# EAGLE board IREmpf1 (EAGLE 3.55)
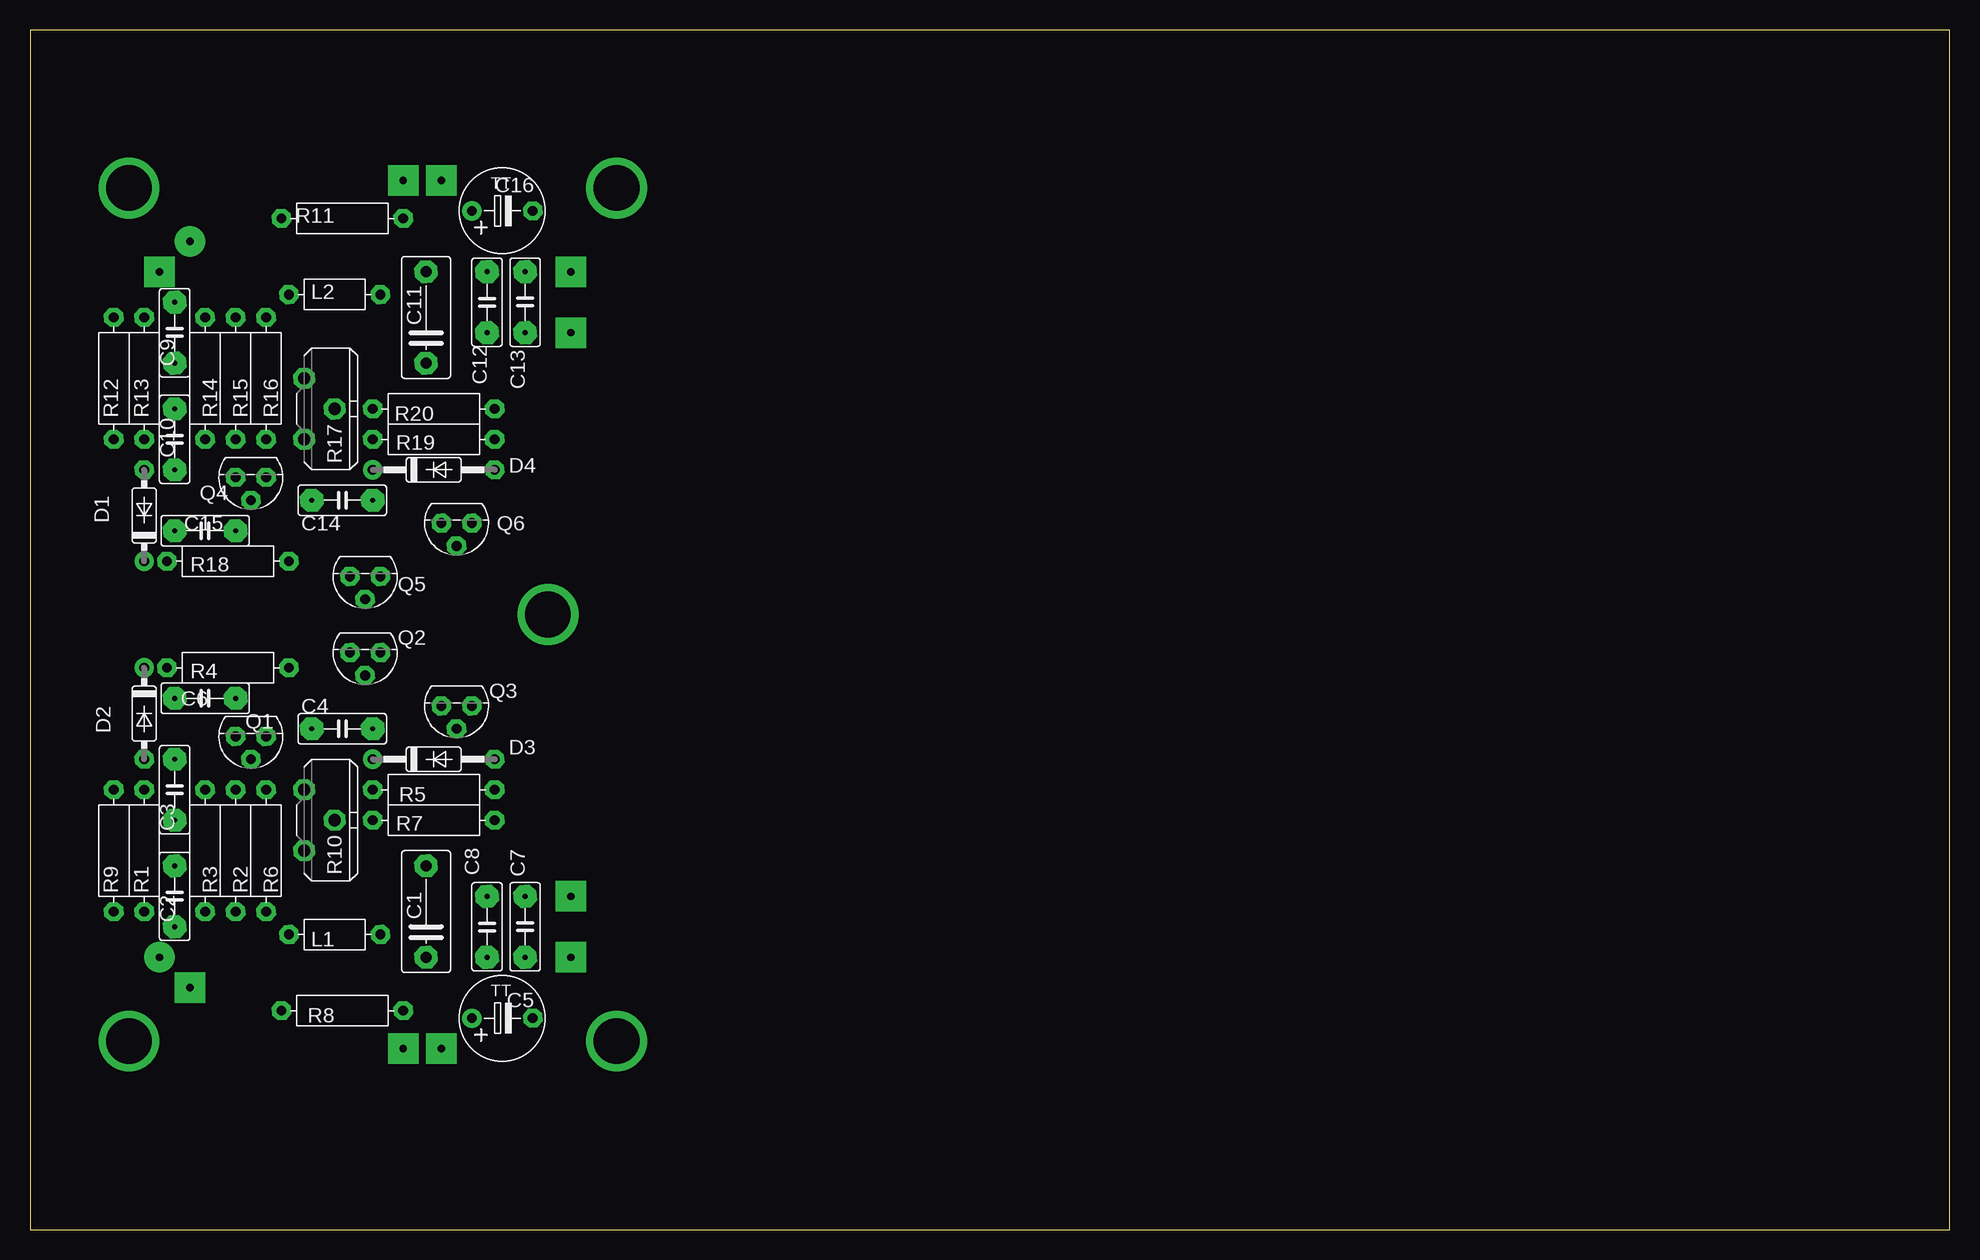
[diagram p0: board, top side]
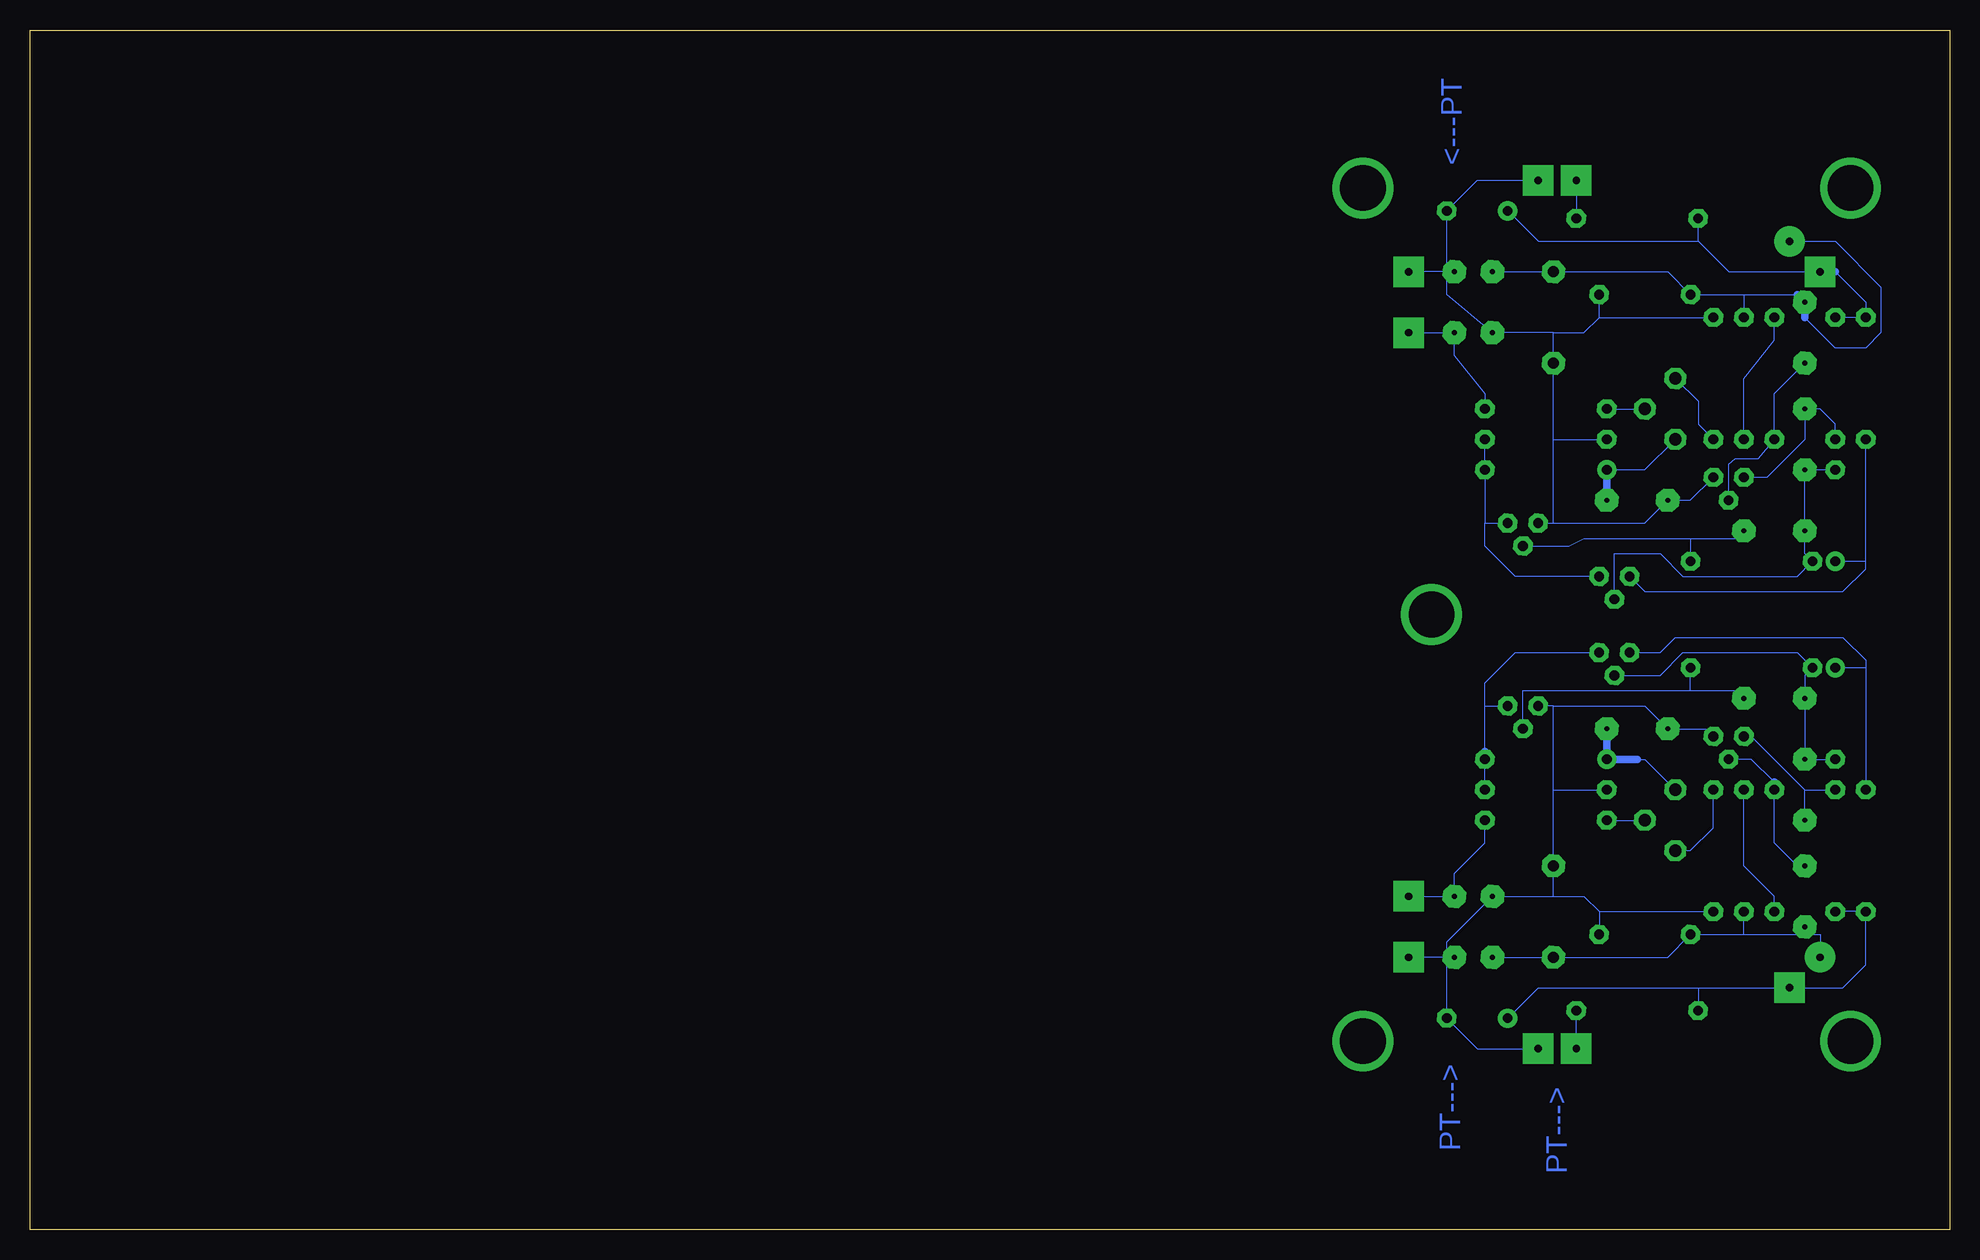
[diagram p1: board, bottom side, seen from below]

Size 160 x 100 mm. Coordinates in mm from the lower left corner, seen from the top.
Outline: 0,0 160,0 160,100 0,100 0,0
Copper layers used: Bottom

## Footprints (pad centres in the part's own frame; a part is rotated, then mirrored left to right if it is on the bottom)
,5B4 = drill 0.914 pad 1.905 octagon:  -3.81,0;  3.81,0
B2,5 = drill 0.406 pad 1.93 octagon:  -2.54,0;  2.54,0
5D7 = drill 0.813 pad 1.6 octagon:  -2.54,0 | drill 0.813 pad 1.6 round:  2.54,0
35-7 = drill 0.813 pad 1.6 round:  -3.81,0 | drill 0.813 pad 1.6 octagon:  3.81,0
35-10 = drill 0.813 pad 1.6 round:  -5.08,0 | drill 0.813 pad 1.6 octagon:  5.08,0
7,5 = drill 0.813 pad 1.6 octagon:  -3.81,0;  3.81,0
92 = drill 0.813 pad 1.6 octagon:  1.27,0;  0,1.905;  -1.27,0
10 = drill 0.813 pad 1.6 octagon:  -5.08,0;  5.08,0
-10S = drill 1.016 pad 1.778 octagon:  -2.54,-1.27;  2.54,-1.27;  0,1.27

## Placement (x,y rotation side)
C1  560p  [,5B4]  33.02,26.5 90 top
C2  0,1æ  [B2,5]  12.06,27.77 90 top
C3  0,1æ  [B2,5]  12.06,36.66 90 top
C4  0,1æ  [B2,5]  26.03,41.74 0 top
C5  47æ  [5D7]  39.37,17.61 180 top
C6  0,1æ  [B2,5]  14.6,44.28 180 top
C7  ??  [B2,5]  41.27,25.23 90 top
C8  ??  [B2,5]  38.1,25.23 270 top
C9  0,1æ  [B2,5]  12.06,74.77 90 top
C10  0,1æ  [B2,5]  12.06,65.88 90 top
C11  560p  [,5B4]  33.02,76.03 90 top
C12  ??  [B2,5]  38.1,77.3 270 top
C13  ??  [B2,5]  41.27,77.3 90 top
C14  0,1æ  [B2,5]  26.03,60.8 0 top
C15  0,1æ  [B2,5]  14.6,58.25 180 top
C16  47æ  [5D7]  39.37,84.92 180 top
D1  1N4148  [35-7]  9.52,59.52 90 top
D2  1N4148  [35-7]  9.52,43.02 270 top
D3  1N4148  [35-10]  33.65,39.2 0 top
D4  1N4148  [35-10]  33.65,63.34 0 top
L1  68m  [7,5]  25.39,24.6 180 top
L2  68m  [7,5]  25.39,77.94 180 top
Q1  BC560C  [92]  18.41,41.11 180 top
Q2  BC560C  [92]  27.93,48.09 180 top
Q3  BC238C  [92]  35.55,43.65 180 top
Q4  BC560C  [92]  18.41,62.7 180 top
Q5  BC560C  [92]  27.93,54.45 180 top
Q6  BC238C  [92]  35.55,58.89 180 top
R1  10k  [10]  9.52,31.58 270 top
R2  1M  [10]  17.14,31.58 270 top
R3  1M  [10]  14.6,31.58 270 top
R4  1M  [10]  16.5,46.82 0 top
R5  1k  [10]  33.65,36.66 180 top
R6  22k  [10]  19.68,31.58 270 top
R7  ??  [10]  33.65,34.12 0 top
R8  470  [10]  26.03,18.25 180 top
R9  10  [10]  6.98,31.58 270 top
R10  10k  [-10S]  24.12,34.12 270 top
R11  470  [10]  26.03,84.29 180 top
R12  10  [10]  6.98,70.95 270 top
R13  10k  [10]  9.52,70.95 270 top
R14  1M  [10]  14.6,70.95 270 top
R15  1M  [10]  17.14,70.95 270 top
R16  22k  [10]  19.68,70.95 270 top
R17  10k  [-10S]  24.12,68.41 270 top
R18  1M  [10]  16.5,55.71 0 top
R19  1k  [10]  33.65,65.88 0 top
R20  ??  [10]  33.65,68.41 180 top

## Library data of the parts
C1-C4 C6-C15 = CAP
C5 C16 = CAP-TANT
D1-D4 = DIODE
L1 L2 R1-R20 = DISCRETE
Q1 Q2 Q4 Q5 = PNP
Q3 Q6 = NPN

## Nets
N$1: D2. Q2. R9.
N$2: C5. R1. R8. R9.
N$3: C3. Q1. R1.
N$4: C2. Q1. R3.
N$5: R2. R3.
N$6: C1. C2. C8. L1. R2.
N$7: D3. Q2. Q3. R5.
N$8: C1. C4. C5. C7. C8. L1. Q1. Q3. R5. R6.
N$9: C4. D3. R10.
N$10: C6. Q3. R4.
N$11: C3. C6. D2. Q2. R4.
N$16: R7. R10.
N$17: C7. R7.
N$18: R8.
S$1: R6. R10.
S$2: C11. C12. C13. C14. C16. L2. Q4. Q6. R16. R19.
S$3: R11.
S$4: C16. R11. R12. R13.
S$7: C13. R20.
S$9: R17. R20.
S$10: R16. R17.
S$11: C14. D4. R17.
S$12: D4. Q5. Q6. R19.
S$14: C15. Q6. R18.
S$15: D1. Q5. R12.
S$16: C10. C15. D1. Q5. R18.
S$18: C10. Q4. R13.
S$19: C9. Q4. R14.
S$20: R14. R15.
S$21: C9. C11. C12. L2. R15.

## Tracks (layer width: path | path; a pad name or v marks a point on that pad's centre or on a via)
N$1
  Bottom 0: 6.98,46.82 9.52,46.82 | 6.98,46.82 6.98,36.66 | 6.98,46.82 6.98,47.46 8.89,49.37 22.86,49.37 24.12,48.09 26.66,48.09
N$2  (via drill 0.61 pad 2.54)
  Bottom 0: R1. R9. 6.98,22.06 8.89,20.15 v13.33,20.15 20.95,20.15 | C5. 34.29,20.15 20.95,20.15 | 20.95,20.15 R8.
N$3
  Bottom 0: 17.14,41.11 16.5,41.11 12.06,36.66 | 12.06,34.12 12.06,36.66 | 12.06,36.66 9.52,36.66
N$4
  Bottom 0: 14.6,37.3 16.5,39.2 18.41,39.2 | 14.6,36.66 14.6,32.22 12.7,30.31 C2.
  Bottom 0.61: 14.6,36.66 14.6,37.3
N$5
  Bottom 0: R3. 14.6,27.77 17.14,30.31 17.14,36.66
N$6  (via drill 0.61 pad 2.54)
  Bottom 0: C8. 33.02,22.7 23.49,22.7 L1. | L1. 12.7,24.6 | 12.7,24.6 10.79,24.6 v10.79,22.7 | L1. 17.14,24.6 R2. | 12.7,24.6 12.06,24.6 12.06,25.23
N$7
  Bottom 0: 38.73,43.65 38.73,45.55 36.19,48.09 Q2. | 38.73,36.66 38.73,39.84 38.73,43.65 | 38.73,43.65 Q3.
  Bottom 0.61: 38.73,39.84 D3.
N$8  (via drill 0.61 pad 2.54)
  Bottom 0: Q1. 20.31,41.74 23.49,41.74 25.39,43.65 33.02,43.65 | 33.02,43.65 34.29,43.65 | 33.02,36.66 R5. | 33.02,36.66 33.02,43.65 | 29.2,26.5 R6. | 29.2,26.5 29.2,24.6 | 33.02,36.66 C1. 33.02,27.77 38.1,27.77 | 29.2,26.5 30.47,27.77 38.1,27.77 | 38.1,27.77 41.91,23.96 41.91,22.7 | 41.91,22.7 v45.08,22.7 | 41.91,22.7 41.27,22.7 41.91,22.06 41.91,17.61 39.37,15.08 v34.29,15.08
N$9
  Bottom 0: C4. 28.57,39.2 25.39,39.2 22.86,36.66
  Bottom 0.61: 26.03,39.2 28.57,39.2 C4.
N$10
  Bottom 0: 21.58,44.92 17.77,44.92 17.14,44.28 | 21.58,44.92 35.55,44.92 35.55,41.74 | 21.58,44.92 R4.
N$11
  Bottom 0: 27.93,46.19 24.12,46.19 22.22,48.09 12.7,48.09 11.43,46.82 12.06,46.19 C6. C3. D2.
N$16
  Bottom 0: 28.57,34.12 R10.
N$17  (via drill 0.61 pad 2.54)
  Bottom 0: R7. 38.73,32.22 41.27,29.68 C7. v45.08,27.77
N$18  (via drill 0.61 pad 2.54)
  Bottom 0: v31.11,15.08 31.11,18.25
S$1
  Bottom 0: 22.86,31.58 21.58,31.58 19.68,33.49 19.68,36.66
S$2  (via drill 0.61 pad 2.54)
  Bottom 0: v34.29,87.47 39.37,87.47 41.91,84.92 41.91,79.84 41.91,77.94 C12. 33.02,74.77 | 33.02,74.77 33.02,72.22 33.02,65.88 | 33.02,74.77 30.47,74.77 29.2,76.03 | 29.2,76.03 29.2,77.94 | 29.2,76.03 19.68,76.03 | 33.02,58.89 33.02,65.88 | 33.02,65.88 28.57,65.88 | 33.02,58.89 25.39,58.89 23.49,60.8 21.58,60.8 Q4. | 34.29,58.89 33.02,58.89 | C13. v45.08,79.84
  Bottom 0.61: 41.91,79.84 C13.
S$3  (via drill 0.61 pad 2.54)
  Bottom 0: v31.11,87.47 31.11,84.29
S$4  (via drill 0.61 pad 2.54)
  Bottom 0: 20.95,82.39 18.41,79.84 v10.79,79.84 | 9.52,79.84 6.98,77.3 6.98,76.03 9.52,76.03 | C16. 34.29,82.39 20.95,82.39 | 20.95,82.39 R11.
  Bottom 0.61: v10.79,79.84 9.52,79.84
S$5  (via drill 3.81 pad 5.08)
  other vias: 8.25,15.71
S$6  (via drill 3.81 pad 5.08)
  other vias: 48.89,15.71
S$7  (via drill 0.61 pad 2.54)
  Bottom 0: v45.08,74.77 41.27,74.77 41.27,72.86 38.73,69.69 38.73,68.41
S$8  (via drill 3.81 pad 5.08)
  other vias: 48.89,86.83
S$9
  Bottom 0: R20. R17.
S$10
  Bottom 0: 22.86,70.95 20.95,69.05 20.95,67.14 R16.
S$11
  Bottom 0: C14. 28.57,63.34 25.39,63.34 22.86,65.88
  Bottom 0.61: 28.57,63.34 C14.
S$12
  Bottom 0: R19. D4. 38.73,58.89 | Q5. 36.19,54.45 38.73,56.98 38.73,58.89 | 38.73,58.89 Q6.
S$13  (via drill 3.81 pad 5.08)
  other vias: 8.25,86.83
S$14
  Bottom 0: 35.55,56.98 31.74,56.98 30.47,57.62 21.58,57.62 | 21.58,57.62 17.14,57.62 17.14,58.25 | 21.58,57.62 R18.
S$15
  Bottom 0: 26.66,54.45 25.39,53.17 8.89,53.17 6.98,55.08 6.98,55.71 | 9.52,55.71 6.98,55.71 | 6.98,55.71 R12.
S$16
  Bottom 0: D1. 12.06,63.34 C15. 12.06,56.35 11.43,55.71 12.7,54.45 22.22,54.45 24.12,56.35 27.93,56.35 27.93,52.54
S$17  (via drill 3.81 pad 5.08)
  other vias: 43.18,51.27
S$18
  Bottom 0: R13. 9.52,67.14 10.79,68.41 C10. 12.06,65.88 15.24,62.7 17.14,62.7
S$19
  Bottom 0: 18.41,60.8 18.41,63.8 17.84,64.27 15.94,64.27 R14. 14.6,69.69 12.06,72.22
S$20
  Bottom 0: R15. 17.14,70.95 14.6,74.13 14.6,76.03
S$21  (via drill 0.61 pad 2.54)
  Bottom 0: v13.33,82.39 9.52,82.39 5.71,78.58 5.71,74.77 6.98,73.5 9.52,73.5 12.06,76.03 | 17.14,77.94 17.14,76.03 | 17.14,77.94 12.7,77.94 | 17.14,77.94 L2. 23.49,79.84 C11. 38.1,79.84
  Bottom 0.61: 12.7,77.94 C9. 12.06,76.03

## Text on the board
Bottom: <---PT | PT---> | PT--->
